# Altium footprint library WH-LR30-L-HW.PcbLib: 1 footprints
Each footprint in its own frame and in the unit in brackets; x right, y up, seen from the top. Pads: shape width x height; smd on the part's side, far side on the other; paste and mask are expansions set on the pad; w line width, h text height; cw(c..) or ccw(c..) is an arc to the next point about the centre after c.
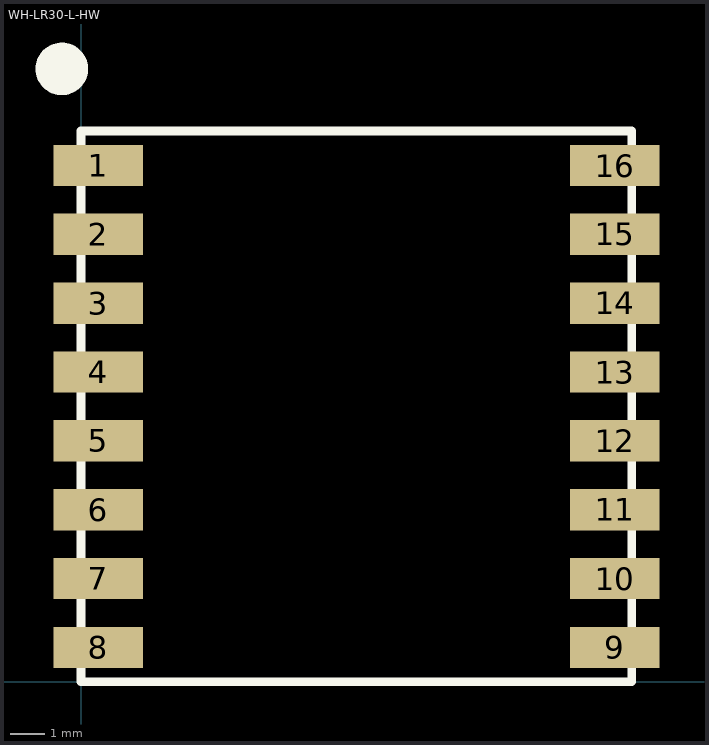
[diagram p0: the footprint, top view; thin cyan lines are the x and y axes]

## WH-LR30-L-HW [mm]
height 2.13
pads (16):
  rect 2.6x1.2 smd mask+0.025: 1(0.5,15) 2(0.5,13) 3(0.5,11) 4(0.5,9) 5(0.5,7) 6(0.5,5) 7(0.5,3) 8(0.5,1) 9(15.5,1) 10(15.5,3) 11(15.5,5) 12(15.5,7) 13(15.5,9) 14(15.5,11) 15(15.5,13) 16(15.5,15)
Top Overlay:
  circle w0.762: c-0.559,17.805 r0.381
  lines w0.254: 0,0 16.002,0 16.002,16.002 0,16.002 0,0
